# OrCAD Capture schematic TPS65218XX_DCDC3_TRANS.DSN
size E; title: TPS65218D0 Power Management for ARM® Cortex™-A8/A9; rev: 1.0; note: Datasheet:SLDS234B     EVM:NA; note: Synchronous Step Down Converter
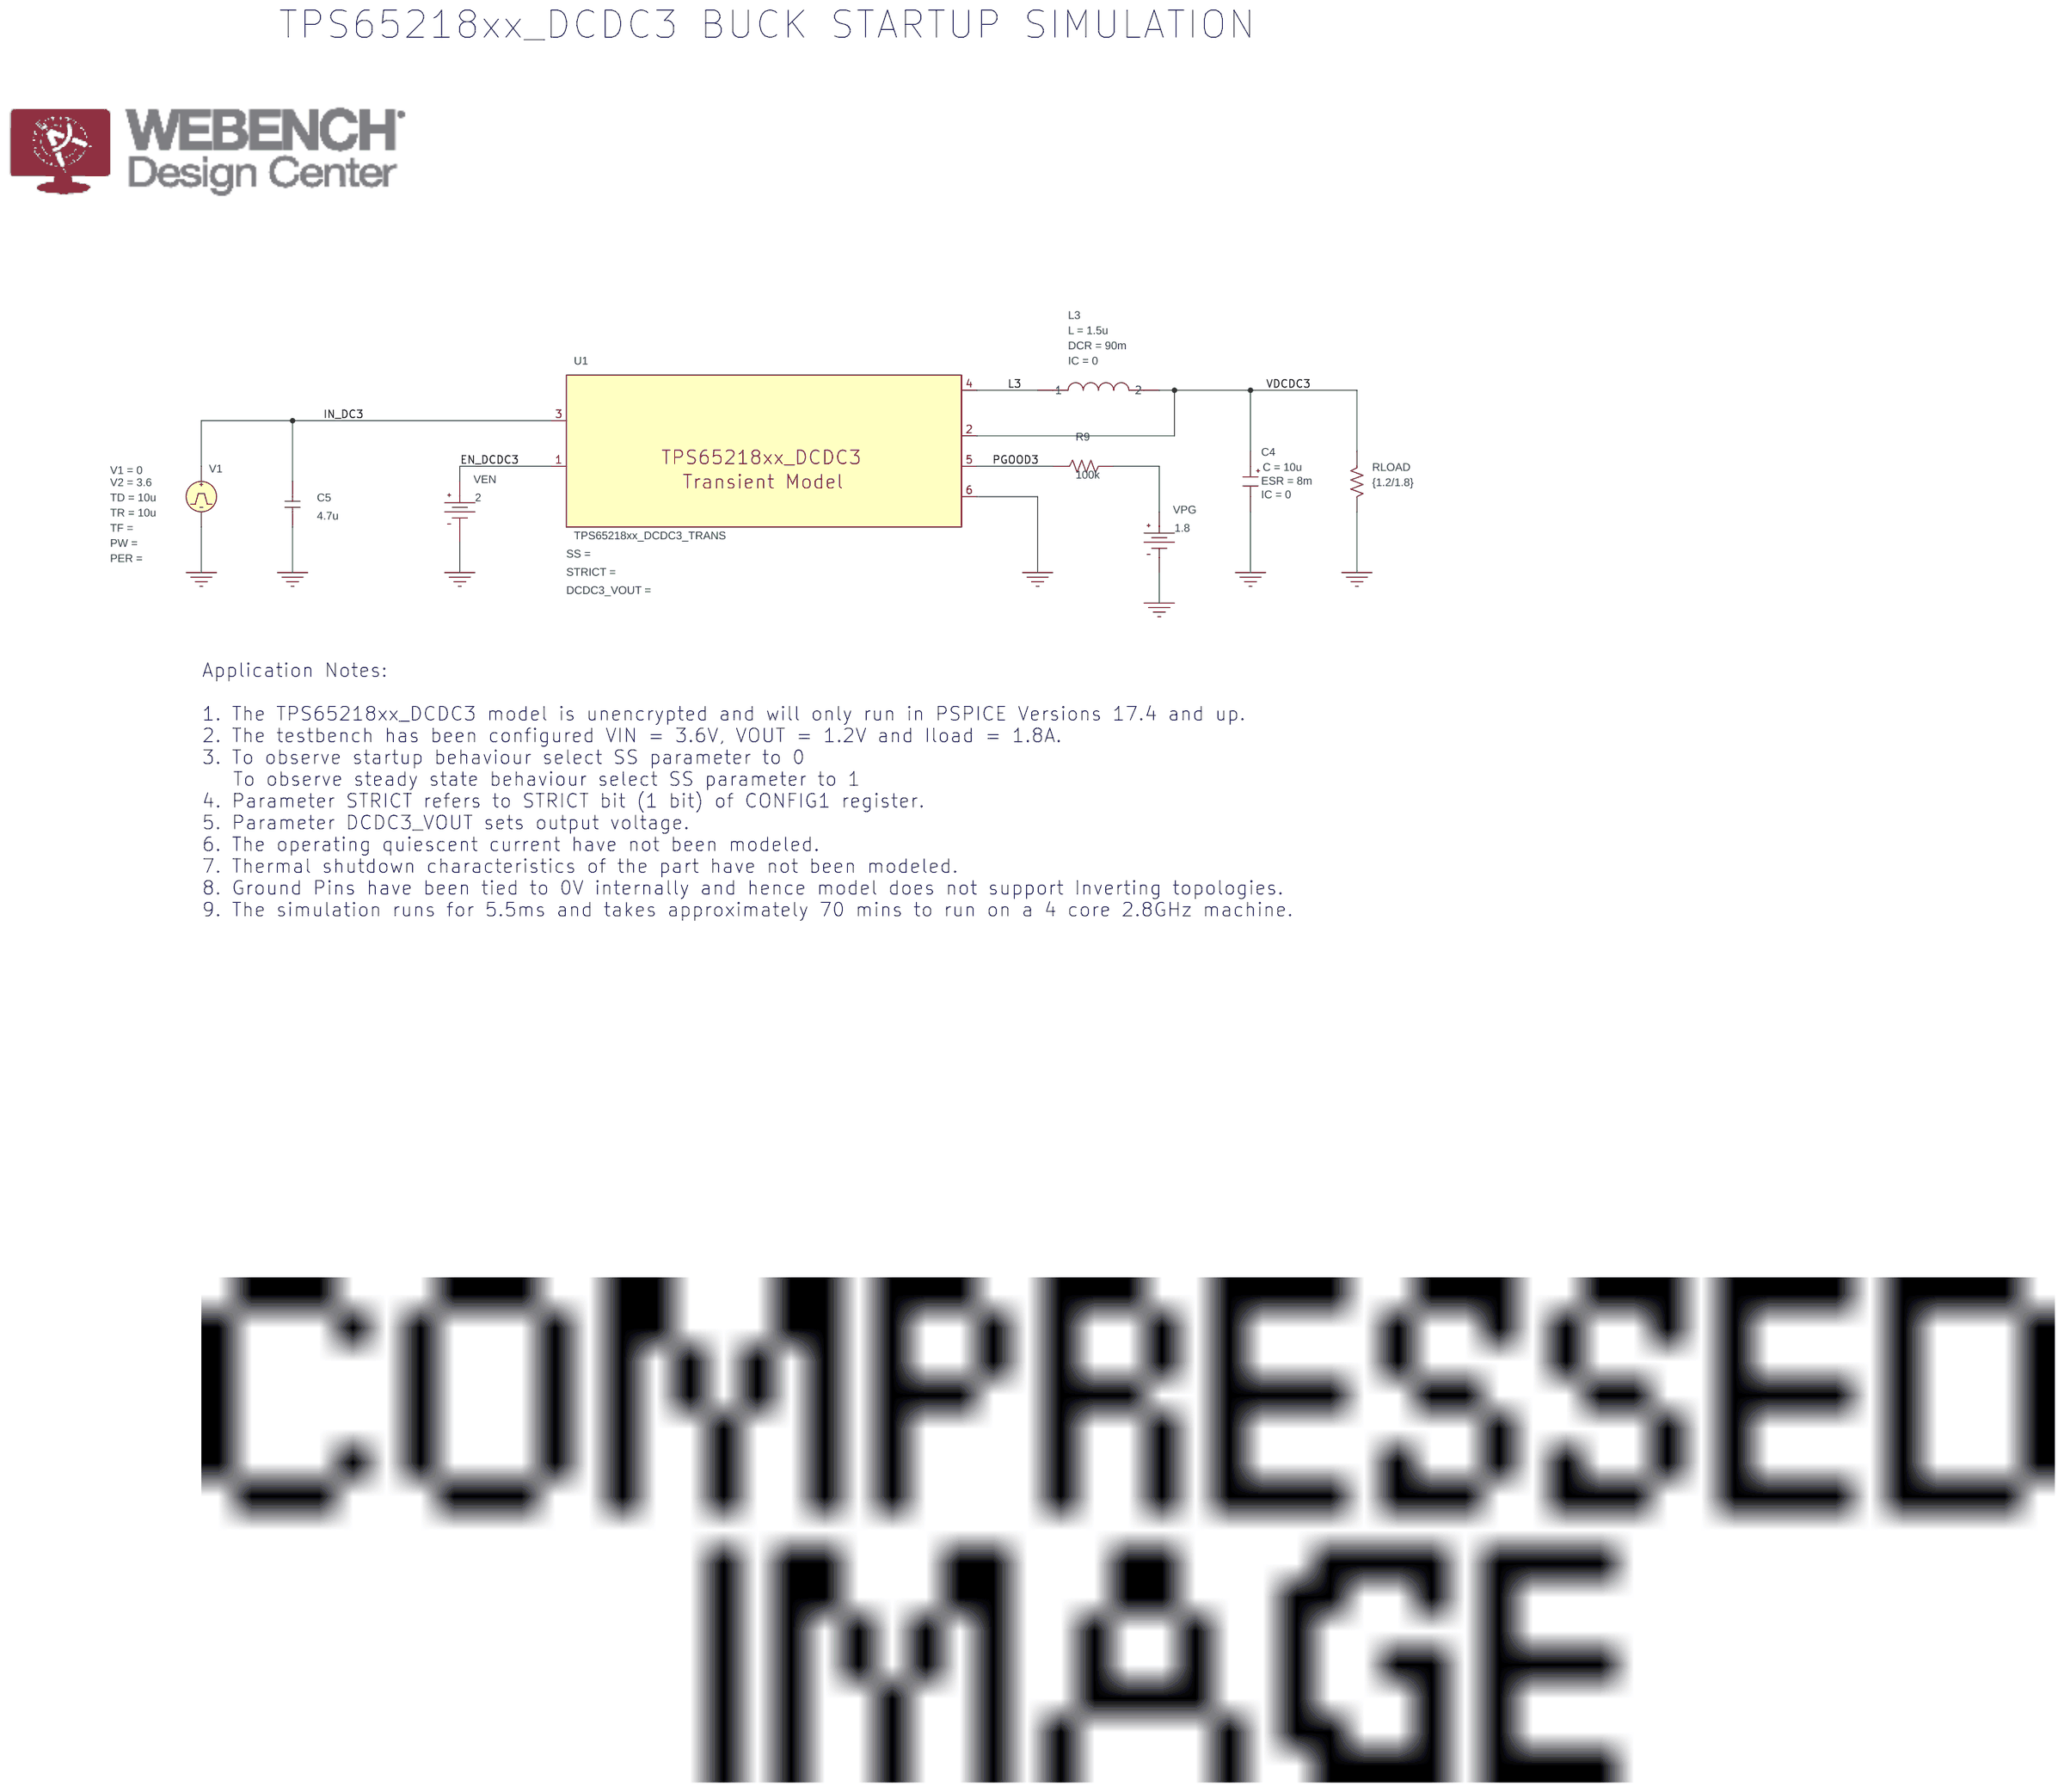
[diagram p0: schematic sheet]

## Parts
C4  CESR
C5  4.7u  [RAD/CK05]
L3  LDCR
R9  100k  [AX/RC05]
RLOAD  {1.2/1.8}  [AX/RC05]
U1  TPS65218xx_DCDC3_TRANS
V1  VPULSE
VEN  VDC
VPG  VDC

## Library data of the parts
C4 = CESR_0: C: 10u; ESR: 8m; IC: 0; PSpiceTemplate: X^@REFDES %IN %OUT @MODEL PARAMS:  ?C|C=@C||C=100u|  ?ESR|ESR=@ESR||ESR=0.01| ?X|X=@X||X=2|  ?IC|IC=@IC||IC=2|; X: 1
C5 = C
L3 = LDCR: DCR: 90m; IC: 0; L: 1.5u
R9 RLOAD = R
U1 = TPS65218XX_DCDC3_TRANS
V1 = VPULSE: TD: 10u; TR: 10u; V1: 0; V2: 3.6
VEN = VDC: DC: 2
VPG = VDC: DC: 1.8

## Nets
0: C4.2(OUT) C5.1 RLOAD.2 U1.6(POWER_PAD) V1.2(-) VEN.1(-) VPG.1(-)
EN_DCDC3: U1.1(EN_DCDC3) VEN.0(+)
IN_DC3: C5.2 U1.3(IN_DCDC3) V1.1(+)
L3: L3.1 U1.4(L3)
PGOOD3: R9.1 U1.5(PGOOD3)
VDCDC3: C4.1(IN) L3.2 RLOAD.1 U1.2(FB3)
N16774093: R9.2 VPG.0(+)

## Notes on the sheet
- TPS65218xx_DCDC3 BUCK STARTUP SIMULATION
- Application Notes:
  1. The TPS65218xx_DCDC3 model is unencrypted and will only run in PSPICE Versions 17.4 and up.
  2. The testbench has been configured VIN = 3.6V, VOUT = 1.2V and Iload = 1.8A.
  3. To observe startup behaviour select SS parameter to 0
     To observe steady state behaviour select SS parameter to 1
  4. Parameter STRICT refers to STRICT bit (1 bit) of CONFIG1 register.
  5. Parameter DCDC3_VOUT sets output voltage.
  6. The operating quiescent current have not been modeled.
  7. Thermal shutdown characteristics of the part have not been modeled.
  8. Ground Pins have been tied to 0V internally and hence model does not support Inverting topologies.
  9. The simulation runs for 5.5ms and takes approximately 70 mins to run on a 4 core 2.8GHz machine.
